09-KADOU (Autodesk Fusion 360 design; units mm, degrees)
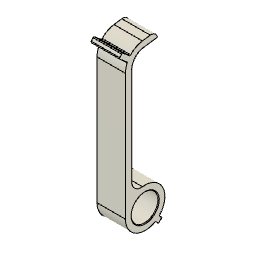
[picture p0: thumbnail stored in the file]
sketch "スケッチ1" plane through (0, 0, 0) normal (1, 0, 0) x axis (0, 0, -1)
  circle C1 centre (0, 0) radius 6.25
  point P1 (0, 0)
  point P2 (0, 0)
  coincident P1 P2
  dimension "d1" diameter C1 = 12.5
extrude "押し出し1" new body sketch "スケッチ1" distance 9
sketch "スケッチ2" plane through (0, 0, 0) normal (1, 0, 0) x axis (0, 0, -1)
  line L1 (-4.25, 0) -> (-4.25, 40)
  line L2 (-6.25, 0) -> (-4.25, 0)
  line L3 (-6.25, 40) -> (-6.25, 0)
  line L4 (3.8647, 44.8349) -> (-0.5915, 44.2086)
  line L5 (3.5864, 46.8155) -> (3.8647, 44.8349)
  line L6 (-0.8698, 46.1892) -> (3.5864, 46.8155)
  circle C1 centre (0, 0) radius 6.25
  arc A1 centre (0, 40) radius 4.25 clockwise from (-4.25, 40) to (-0.5915, 44.2086)
  arc A2 centre (0, 40) radius 6.25 clockwise from (-6.25, 40) to (-0.8698, 46.1892)
  point P1 (0, 0)
  point P8 (0, 40)
  point P12 (0, 40)
  vertical L1
  horizontal L2
  vertical L3
  coincident P1 L2
  tangent L3 C1
  perpendicular L4 L5
  perpendicular L5 L6
  coincident P8 P12
  vertical P1 P8
  tangent L1 A1
  tangent A1 L4
  tangent L3 A2
  dimension "d5" distance L1 L3 = 2
  dimension "d18" distance L4 L6 = 2
  dimension "d21" distance P8 L5 = 4.5
  dimension "d22" angle L1 L4 = 98
  dimension "d54" distance P1 P12 = 40
extrude "押し出し2" add sketch "スケッチ2" profile of L1 L3 C1 distance 9
sketch "スケッチ4" plane through (0, 0, 0) normal (1, 0, 0) x axis (0, 0, -1)
  line L1 (5.3033, -5.3033) -> (0, 0)
  line L2 (4.2426, -6.364) -> (5.3033, -5.3033)
  line L3 (-1.0607, -1.0607) -> (4.2426, -6.364)
  line L4 (0, 0) -> (-1.0607, -1.0607)
  line L5 (-22.5, 0) -> (-1.75, 0)
  point P1 (0, 0)
  point P2 (0, 0)
  perpendicular L1 L2
  parallel L1 L3
  parallel L2 L4
  coincident P1 P2
  dimension "d24" angle L1 L5 = 45
  dimension "d25" distance L2 L4 = 7.5
  dimension "d26" distance L1 L3 = 1.5
extrude "押し出し4" add sketch "スケッチ4" profile of L1 L2 L3 L4 distance 9
joint_origin "JointOrigin1" OffsetX 0 OffsetY 0 OffsetZ 0 AngleZ 0
sketch "スケッチ5" plane through (0, 0, 0) normal (1, 0, 0) x axis (0, 0, -1)
  line L1 (0, 40) -> (-7.2774, 46.1065)
  line L2 (-0.9642, 38.8509) -> (0, 40)
  line L3 (-8.2416, 44.9574) -> (-0.9642, 38.8509)
  line L4 (-7.2774, 46.1065) -> (-8.2416, 44.9574)
  line L5 (0, 22.5) -> (0, 1.75)
  arc A1 centre (0, 40) radius 4.25 clockwise from (-4.25, 40) to (-0.5915, 44.2086)
  point P3 (0, 40)
  point P8 (0, 40)
  perpendicular L1 L2
  parallel L1 L3
  parallel L2 L4
  coincident P3 P8
  dimension "d33" angle L1 L5 = 50
  dimension "d34" distance L1 L3 = 1.5
  dimension "d35" distance L2 L4 = 9.5
extrude "押し出し5" add sketch "スケッチ5" profile of L1 L3 L4 A1 distance 9
fillet "フィレット3" radius 2
sketch "スケッチ6" plane through (0, 43.4339, 6.1042) normal (0, -0.9903, -0.1392) x axis (-1, 0, 0)
  line L1 (-4.5, 10.0669) -> (4.5, 10.0669)
  line L2 (-4.5, 5.5669) -> (-4.5, 10.0669)
  line L3 (4.5, 5.5669) -> (-4.5, 5.5669)
  line L4 (4.5, 10.0669) -> (4.5, 5.5669)
  circle C1 centre (0, 8.0669) radius 0.75
  point P1 (0, 0)
  point P6 (0, 8.0669)
  vertical P1 P6
  dimension "d40" distance L1 P6 = 2
  dimension "d41" diameter C1 = 1.5
extrude "押し出し6" add sketch "スケッチ6" profile of C1 along normal blind 0.7
fillet "フィレット4" radius 0.6
fillet "フィレット5" radius 3
fillet "フィレット6" radius 0.3
hole "穴" HoleDepth 9 HoleDiameter 8.5 TipAngle 118
chamfer "面取り" distance 0.2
